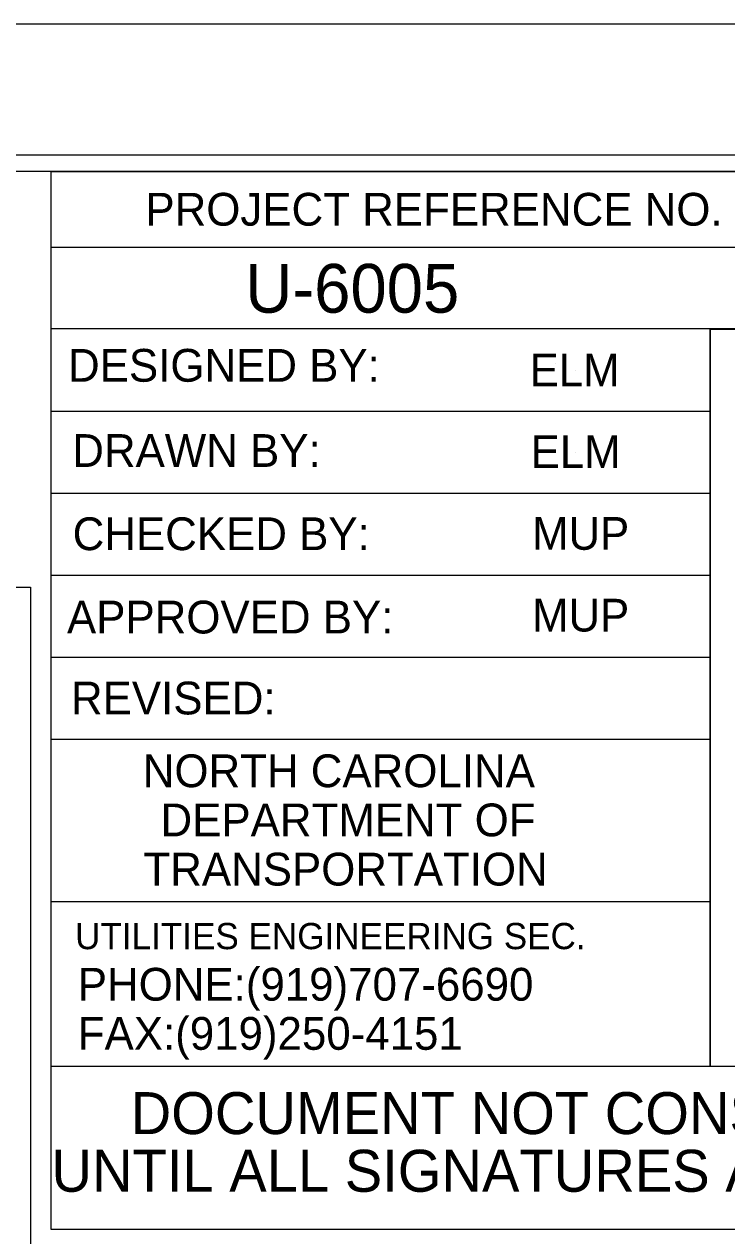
# Model space of a CAD drawing. Extents: x 0 to 4772457, y -312190 to 1506.
# Drawn here: x 2.465 to 2.644, y 1.5246 to 1.8333 of the extents above; entities that cross this region are included whole.
import ezdxf

# ---------------------------------------------------------------- set-up
doc = ezdxf.new("R2010")
doc.units = 0
for name, color, linetype in [('Detection Chart CELL', 7, 'Continuous'), ('Legend CELL', 7, 'Continuous'), ('Old_Level_63', 7, 'Continuous'), ('Timing Chart CELL', 7, 'Continuous')]:
    doc.layers.add(name, color=color, linetype=linetype)

msp = doc.modelspace()

# ---------------------------------------------------------------- linework, layer by layer
at = {"layer": 'Legend CELL'}
for p, q in [((2.4719, 1.77648), (2.80496, 1.77648)), ((2.55581, 1.76604), (2.55581, 1.76604)), ((2.6054, 1.74516), (2.6054, 1.74516)), ((2.4719, 1.7347), (2.63979, 1.7347)), ((2.6054, 1.72427), (2.6054, 1.72427)), ((2.4719, 1.71383), (2.63979, 1.71383)), ((2.6054, 1.70339), (2.6054, 1.70339)), ((2.4719, 1.69295), (2.63979, 1.69295)), ((2.6054, 1.68252), (2.6054, 1.68252)), ((2.4719, 1.67208), (2.63979, 1.67208)), ((2.4719, 1.65118), (2.63979, 1.65118)), ((2.4719, 1.60977), (2.63979, 1.60977))]:
    msp.add_line(p, q, dxfattribs=at)
for points in [[(2.4719, 1.79581), (2.80496, 1.79581), (2.80496, 1.75568)], [(2.80496, 1.75568), (2.4719, 1.75568), (2.4719, 1.79581)], [(2.63979, 1.75568), (2.63979, 1.56775), (2.4719, 1.56775), (2.4719, 1.79581)], [(2.80496, 1.56775), (2.63979, 1.56775), (2.63979, 1.7556), (2.80496, 1.7556)]]:
    msp.add_lwpolyline(points, dxfattribs=at)
at = {"layer": 'Old_Level_63'}
for p, q in [((2.60044, 1.74676), (2.60044, 1.74676)), ((2.4719, 1.52621), (2.4719, 1.56775)), ((2.80496, 1.52621), (2.4719, 1.52621))]:
    msp.add_line(p, q, dxfattribs=at)
for points in [[(0.02749, 0.00833), (2.83333, 0.00833), (2.83333, 1.83333), (0.02749, 1.83333)], [(0.04916, 0.04166), (2.82583, 0.04166), (2.82583, 1.8), (0.04916, 1.8)], [(2.80499, 1.79583), (0.30499, 1.79583), (0.30499, 0.04583), (2.80499, 0.04583)]]:
    msp.add_lwpolyline(points, close=True, dxfattribs=at)
at = {"layer": 'Timing Chart CELL'}
msp.add_lwpolyline([(0.37349, 0.92053), (0.37349, 1.68989), (2.46666, 1.68989), (2.46666, 1.49966), (2.75747, 1.49966), (2.75747, 0.92053)], close=True, dxfattribs=at)

# ---------------------------------------------------------------- texts
at = {"layer": 'Detection Chart CELL'}
for s, p in [('DOCUMENT NOT CONSIDERED FINAL ', (2.49215, 1.5505)), ('UNTIL ALL SIGNATURES ARE COMPLETED', (2.47197, 1.53581))]:
    msp.add_text(s, height=0.010697, dxfattribs=at).set_placement(p)
at = {"layer": 'Legend CELL'}
for s, height, p in [('PROJECT REFERENCE NO.', 0.0083524, (2.4959, 1.782)), ('DESIGNED BY:', 0.0083524, (2.47619, 1.74223)), ('DRAWN BY:', 0.008352, (2.47727, 1.72052)), ('CHECKED BY:', 0.0083524, (2.47736, 1.69931)), ('APPROVED BY:', 0.0083524, (2.47592, 1.67808)), ('REVISED:', 0.008352, (2.47694, 1.65745)), ('NORTH CAROLINA', 0.0083524, (2.49523, 1.63891)), ('DEPARTMENT OF', 0.0083524, (2.49975, 1.62639)), ('TRANSPORTATION', 0.0083524, (2.4954, 1.61385)), ('UTILITIES ENGINEERING SEC.', 0.0066819, (2.47799, 1.59763)), ('PHONE:(919)707-6690', 0.0083524, (2.47867, 1.58451)), ('FAX:(919)250-4151', 0.0083524, (2.47867, 1.57199))]:
    msp.add_text(s, height=height, dxfattribs=at).set_placement(p)
at = {"layer": 'Old_Level_63'}
for s, height, p in [('U-6005', 0.01243, (2.52136, 1.75982)), ('ELM', 0.008333, (2.59379, 1.74103)), ('ELM', 0.008333, (2.59408, 1.72025)), ('MUP', 0.008333, (2.59442, 1.69941)), ('MUP', 0.008333, (2.59442, 1.67858))]:
    msp.add_text(s, height=height, dxfattribs=at).set_placement(p)

doc.saveas('drawing.dxf')
